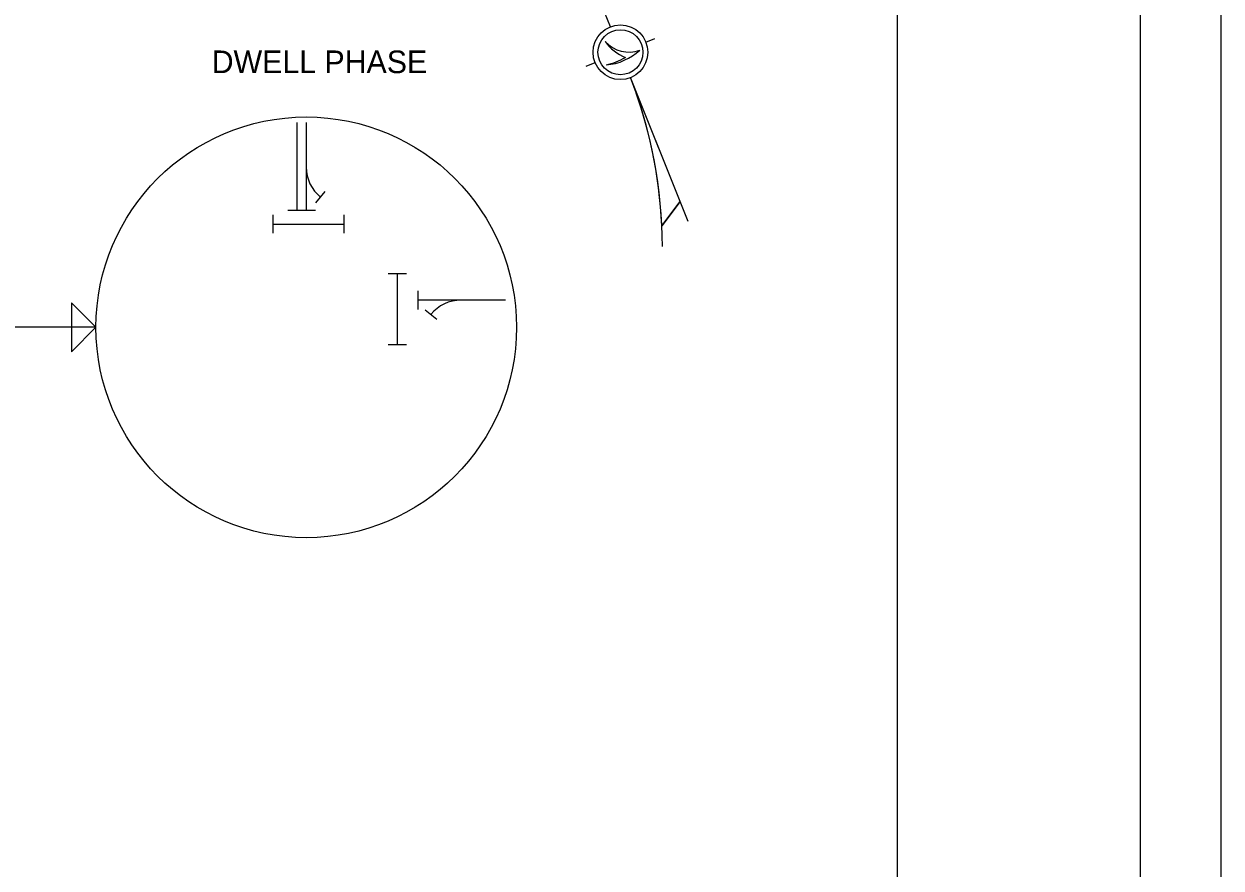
# Model space of a CAD drawing. Extents: x 0 to 680, y 0 to 440.
# Drawn here: x 532 to 680, y 104.3 to 208.6 of the extents above; entities that cross this region are included whole.
import ezdxf

# ---------------------------------------------------------------- set-up
doc = ezdxf.new("R2010")
doc.units = 0
for name, color, linetype in [('SG_P_Text', 7, 'Continuous'), ('SH_Border', 7, 'Continuous'), ('SH_Cut_Line', 7, 'Continuous'), ('SH_Data', 7, 'Continuous'), ('SH_Text', 7, 'Continuous')]:
    doc.layers.add(name, color=color, linetype=linetype)

msp = doc.modelspace()

# ---------------------------------------------------------------- linework, layer by layer
at = {"layer": 'SG_P_Text'}
for p, q in [((565.79, 196.38), (565.79, 185.57)), ((566.93, 196.38), (566.93, 185.57)), ((566.93, 196.38), (566.93, 190.88)), ((568.13, 186.45), (569.29, 187.88)), ((562.82, 184.99), (562.82, 182.71)), ((564.65, 185.57), (566.93, 185.57)), ((565.79, 185.57), (568.07, 185.57)), ((571.59, 184.99), (571.59, 182.71)), ((562.82, 183.85), (571.59, 183.85)), ((579.34, 177.71), (577.06, 177.71)), ((578.2, 168.93), (578.2, 177.71)), ((580.76, 173.31), (580.76, 175.59)), ((591.57, 174.45), (580.76, 174.45)), ((581.64, 173.25), (583.07, 172.09)), ((591.57, 174.45), (586.07, 174.45)), ((579.34, 168.93), (577.06, 168.93))]:
    msp.add_line(p, q, dxfattribs=at)
msp.add_circle((566.94, 171.09), 25.99, dxfattribs=at)
for centre, start, end in [((571.7, 190.88), 180, 231.2007), ((586.07, 169.68), 90, 141.2007)]:
    msp.add_arc(centre, 4.77, start, end, dxfattribs=at)
at = {"layer": 'SH_Border'}
msp.add_line((640, 10), (640, 430), dxfattribs=at)
msp.add_lwpolyline([(30, 430), (670, 430), (670, 10), (30, 10)], close=True, dxfattribs=at)
at = {"layer": 'SH_Cut_Line'}
msp.add_lwpolyline([(0, 0), (680, 0), (680, 440), (0, 440)], close=True, dxfattribs=at)
at = {"layer": 'SH_Data'}
for p, q in [((604.52, 208.21), (597.41, 225.96)), ((608.91, 206.33), (610.02, 206.77)), ((601.52, 203.37), (602.64, 203.82)), ((614.13, 184.18), (607.03, 201.94)), ((613.16, 186.62), (610.89, 183.63)), ((540.94, 171.09), (505.32, 171.09))]:
    msp.add_line(p, q, dxfattribs=at)
msp.add_lwpolyline([(610.89, 183.63), (613.16, 186.62), (607.03, 201.94)], dxfattribs=at)
msp.add_lwpolyline([(540.94, 171.09), (537.91, 174.13), (537.91, 168.06)], close=True, dxfattribs=at)
for radius in [3.38, 2.78]:
    msp.add_circle((605.77, 205.07), radius, dxfattribs=at)
for centre, radius, start, end in [((606.78, 208.91), 3.82, 220.9677, 291.1812), ((608.31, 209.47), 5.38, 214.6659, 249.1244), ((603.51, 210.29), 6.79, 274.2977, 313.2963), ((602.15, 211.89), 8.57, 282.538, 299.6837), ((551.82, 180.74), 59.14, 0.3157, 21.005), ((551.82, 180.74), 59.14, 2.8039, 21.005)]:
    msp.add_arc(centre, radius, start, end, dxfattribs=at)

# ---------------------------------------------------------------- texts
at = {"layer": 'SH_Text'}
msp.add_text('DWELL PHASE', height=2.8, dxfattribs=at).set_placement((555.25, 202.49))

doc.saveas('drawing.dxf')
